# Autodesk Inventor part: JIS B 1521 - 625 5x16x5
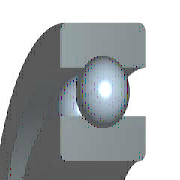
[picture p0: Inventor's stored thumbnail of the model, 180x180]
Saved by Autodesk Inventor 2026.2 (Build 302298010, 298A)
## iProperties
Created: 2025-01
Part Number: JIS B 1521 - 625 5x16x5
Material: 강철, 연강
Description: 깊은 그루부 볼 베어링
Document SubType Name: Modeling
Standard: JIS B 1521
Designer: work
Standard Revision: 2012
Standards Organization: JIS
Language: ko-KR
Size Designation: 625 5x16x5
Categories: <MemberInstance><Categories><Category DisplayName="샤프트 부품" InternalName="7f7aeb1f-a693-4053-b835-cee3144e0d98" Mnemonic="SHFT"><Category DisplayName="베어링" Inter
Density: 7.85 g/cm^3
Appearance: 반연마
IsCustomPart: 1
Author: work
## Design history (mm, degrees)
revolve "본체" stored, may be unused: angle "d6" = 90 deg
revolve "볼" stored, may be unused: angle "d7" = 90 deg
pattern_circular "IDS_ARRAYBALL[SIMPL:T]" dims angle "d3" = 360 deg
body "Solid1"
sketch "스케치" dims "d0" = 2.86 (= -0.26 x WD + 0.26 x BD)
  geometry: L1 (1.07, 5.25)-(3.93, 5.25); L2 (2.5, 5.25)-(2.5, 3.82); L3 (2.5, 5.25)-(2.5, 6.68); L4 (1.437, 4.293)-(0, 4.293); L5 (0, 2.5)-(5, 2.5); L6 (1.437, 6.207)-(0, 6.207); L7 (0, 8)-(5, 8); L8 (5, 2.5)-(5, 4.293); L9 (3.563, 4.293)-(5, 4.293); L10 (3.563, 6.207)-(5, 6.207); L11 (5, 8)-(5, 6.207); L12 (-1.4, 0)-(8.4, 0) reference; L13 (0, -0.3)-(0, 5.3) reference
  constraints: 22 end point, 3 point on line, 2 collinear, 2 midpoint, 2 perpendicular, 2 symmetric about line, 1 parallel, 14 other
  dimensions: "d9" = 5 diameter of L5 L12 (= WD); "d11" = 16 diameter of L7 L12 (= BD); "d12" = 5 distance between parallel lines of L8 L13 (= KB); "d13" = 8.586 diameter of L9 L12 (= 0.326 x BD + 0.674 x WD)
fillet "모깎기1" dims "d1" = 0.3 (= KRS)
other parameters: "WD" = 5 [user parameter; used in 5 equation terms], "BD" = 16 [user parameter; used in 5 equation terms], "KB" = 5 [user parameter; used in 1 equation term], "KRS" = 0.3 [user parameter; used in 1 equation term], "d4" = 0, "d5" = 0, "d8" = 0, "d14" = 0, "d15" = 0, "BBA" = 0 [user parameter], "BC0" = 670000 [user parameter], "BC" = 1730000 [user parameter], "BR" = 8 (= 0.5 x BD) [user parameter], "WR" = 2.5 (= 0.5 x WD) [user parameter]
